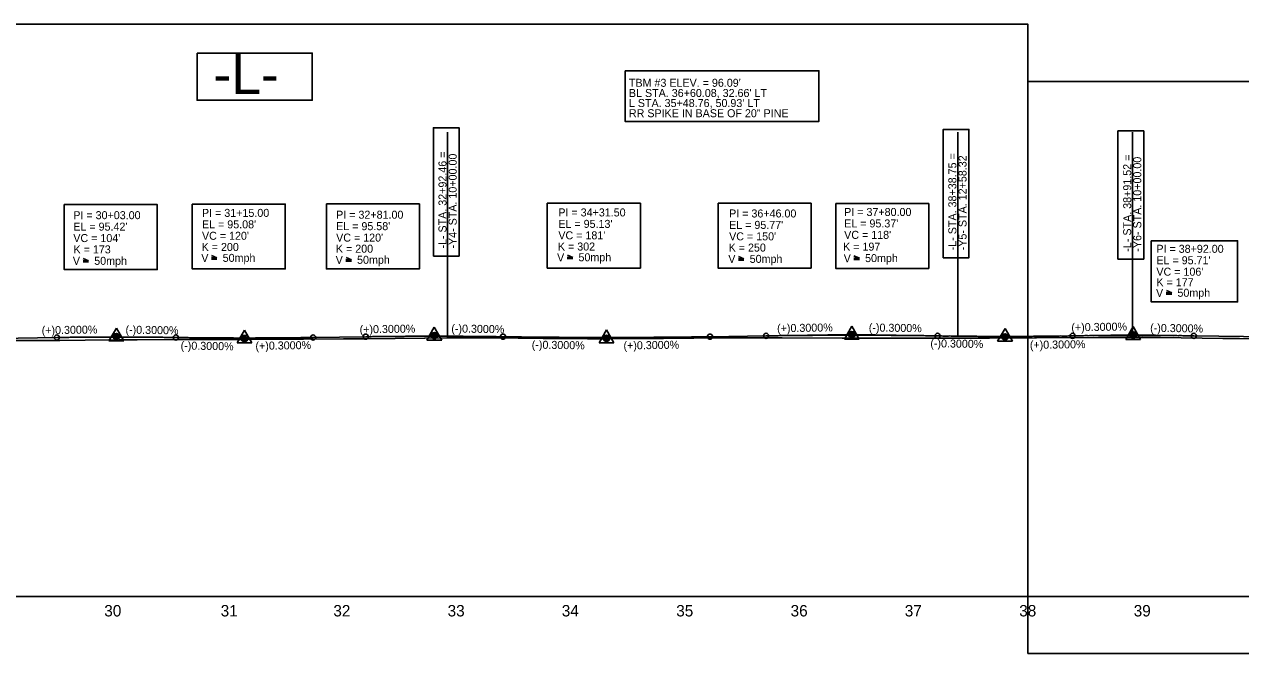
# Model space of a CAD drawing. Extents: x 2366464 to 2375718, y 801842 to 804354.
# Drawn here: x 2369240 to 2370304, y 803804 to 804354 of the extents above; entities that cross this region are included whole.
import ezdxf

# ---------------------------------------------------------------- set-up
doc = ezdxf.new("R2010")
doc.units = 0
for name, color, linetype in [('Exist Profile Cell', 7, 'Continuous'), ('Exist Vertical Profile Ground Line', 7, 'Continuous'), ('Exist Vertical Profile Horizontal Axis Label Major', 7, 'Continuous'), ('Prop Grid Mask', 7, 'Continuous'), ('Prop PFL VPI Symbol CELL', 7, 'Continuous'), ('Prop Vertical Profile Curve Label', 7, 'Continuous'), ('Prop Vertical Profile Grade', 7, 'Continuous'), ('Prop Vertical Profile Grade Label', 7, 'Continuous'), ('Prop VPI Label', 7, 'Continuous'), ('Scratch_Level_5', 7, 'Continuous'), ('Sheet Layout Profile Border Port 1', 7, 'Continuous'), ('Sheet Layout Profile Border Port 2', 7, 'Continuous')]:
    doc.layers.add(name, color=color, linetype=linetype)

# ---------------------------------------------------------------- blocks, each defined once
blk = doc.blocks.new('Profile VPI Symbol')
at = {"layer": 'Prop PFL VPI Symbol CELL'}
for p, q in [((-0.001, 0.147), (-0.13, -0.077)), ((-0.001, 0.147), (0.129, -0.077)), ((-0.13, -0.077), (0.129, -0.077))]:
    blk.add_line(p, q, dxfattribs=at)
for radius in [0.035, 0.024]:
    blk.add_circle((-0.001, -0.003), radius, dxfattribs=at)

msp = doc.modelspace()

# ---------------------------------------------------------------- linework, layer by layer
at = {"layer": 'Exist Profile Cell'}
msp.add_line((2367318, 803854), (2374481.8, 803854), dxfattribs=at)
at = {"layer": 'Exist Vertical Profile Ground Line'}
msp.add_lwpolyline([(2369218.7, 804077.6), (2369243.4, 804077.7), (2369248.7, 804077.7), (2369271.5, 804077.7), (2369293.8, 804077.9), (2369323.5, 804078.2), (2369324.7, 804078.2), (2369339, 804078.3), (2369375, 804078.5), (2369376.2, 804078.5), (2369384.1, 804078.5), (2369429.3, 804078.6), (2369430.2, 804078.6), (2369431.1, 804078.6), (2369474.4, 804078.7), (2369483.3, 804078.7), (2369484.7, 804078.7), (2369519.6, 804079), (2369536.9, 804079.2), (2369537.6, 804079.2), (2369538.1, 804079.2), (2369564.7, 804079.5), (2369590.5, 804079.8), (2369590.8, 804079.8), (2369609.8, 804079.9), (2369614.6, 804079.9), (2369619.3, 804079.9), (2369624.1, 804079.9), (2369628.8, 804079.9), (2369633.6, 804079.9), (2369642.1, 804079.9), (2369650.1, 804079.9), (2369694.1, 804079.5), (2369695.8, 804079.4), (2369724.9, 804079.3), (2369728.9, 804079.3), (2369732.8, 804079.2), (2369736.8, 804079.2), (2369740.7, 804079.2), (2369744.6, 804079.2), (2369746.4, 804079.2), (2369797.7, 804079.3), (2369799.2, 804079.3), (2369852.7, 804079.9), (2369853.2, 804079.9), (2369902.6, 804080), (2369903.2, 804080), (2369955.6, 804079.7), (2369956.7, 804079.7), (2370010, 804079.7), (2370010.8, 804079.7), (2370011.7, 804079.7), (2370069.1, 804079.7), (2370084.3, 804079.8), (2370123.6, 804079.9), (2370124.2, 804079.9), (2370125.6, 804079.9), (2370179.7, 804080.3), (2370232.6, 804080.3), (2370233.3, 804080.3), (2370233.9, 804080.3), (2370288.5, 804079.5), (2370302.9, 804079.4), (2370343.4, 804079.1)], dxfattribs=at)
at = {"layer": 'Prop Grid Mask'}
for points in [[(2369391.5, 804328.9), (2369492.2, 804328.9), (2369492.2, 804287.6), (2369391.5, 804287.6)], [(2369765.8, 804313.4), (2369935.3, 804313.4), (2369935.3, 804269.2), (2369765.8, 804269.2)], [(2369598.1, 804151.5), (2369598.1, 804263.6), (2369620.6, 804263.6), (2369620.6, 804151.5)], [(2370043.9, 804150), (2370043.9, 804262.1), (2370066.4, 804262.1), (2370066.4, 804150)], [(2370196.7, 804148.8), (2370196.7, 804260.9), (2370219.3, 804260.9), (2370219.3, 804148.8)], [(2369275.4, 804196.4), (2369356.7, 804196.4), (2369356.7, 804139.7), (2369275.4, 804139.7)], [(2369387.3, 804196.9), (2369468.6, 804196.9), (2369468.6, 804140.2), (2369387.3, 804140.2)], [(2369504.6, 804197), (2369585.9, 804197), (2369585.9, 804140.3), (2369504.6, 804140.3)], [(2369697.7, 804197.6), (2369779.1, 804197.6), (2369779.1, 804140.9), (2369697.7, 804140.9)], [(2369847, 804197.6), (2369928.4, 804197.6), (2369928.4, 804140.9), (2369847, 804140.9)], [(2369949.9, 804197.3), (2370031.2, 804197.3), (2370031.2, 804140.6), (2369949.9, 804140.6)], [(2370225.8, 804164.8), (2370301.3, 804164.8), (2370301.3, 804111.4), (2370225.8, 804111.4)]]:
    msp.add_lwpolyline(points, close=True, dxfattribs=at)
at = {"layer": 'Prop Vertical Profile Curve Label'}
for p, q in [((2369291.8, 804147.3), (2369296.6, 804147.3)), ((2369291.8, 804146.3), (2369296.6, 804146.3)), ((2369296.6, 804147.3), (2369291.9, 804149.3)), ((2369408.9, 804149.9), (2369404.2, 804151.9)), ((2369404.2, 804149.9), (2369408.9, 804149.9)), ((2369404.2, 804148.8), (2369408.9, 804148.8)), ((2369521.7, 804148.1), (2369526.4, 804148.1)), ((2369521.7, 804147.1), (2369526.4, 804147.1)), ((2369526.4, 804148.1), (2369521.8, 804150.1)), ((2369715.2, 804150.3), (2369720, 804150.3)), ((2369715.2, 804149.3), (2369720, 804149.3)), ((2369720, 804150.3), (2369715.3, 804152.3)), ((2369864.9, 804149), (2369869.6, 804149)), ((2369864.9, 804148), (2369869.6, 804148)), ((2369869.6, 804149), (2369865, 804151)), ((2369965.8, 804149.7), (2369970.6, 804149.7)), ((2369965.8, 804148.6), (2369970.6, 804148.6)), ((2369970.6, 804149.7), (2369965.9, 804151.7)), ((2370243.7, 804119.3), (2370239, 804121.3)), ((2370238.9, 804119.3), (2370243.7, 804119.3)), ((2370238.9, 804118.3), (2370243.7, 804118.3))]:
    msp.add_line(p, q, dxfattribs=at)
for centre in [(2369269, 804080.3), (2369373, 804080.3), (2369373, 804080.3), (2369493, 804080.3), (2369539, 804081), (2369659, 804081), (2369659, 804081), (2369840, 804081), (2369889, 804081.7), (2370039, 804081.7), (2370039, 804081.7), (2370157, 804081.7), (2370157, 804081.7), (2370263, 804081.7)]:
    msp.add_circle(centre, 2.25, dxfattribs=at)
at = {"layer": 'Prop Vertical Profile Grade'}
for p, q in [((2369218, 804079.5), (2369269, 804080.3)), ((2369493, 804080.3), (2369539, 804081)), ((2369840, 804081), (2369889, 804081.7)), ((2370263, 804081.7), (2370364.5, 804080.2))]:
    msp.add_line(p, q, dxfattribs=at)
for points in [[(2369269, 804080.3), (2369271.1, 804080.3), (2369273.1, 804080.4), (2369275.2, 804080.4), (2369277.3, 804080.4), (2369279.4, 804080.4), (2369281.5, 804080.5), (2369283.5, 804080.5), (2369285.6, 804080.5), (2369287.7, 804080.5), (2369289.8, 804080.5), (2369291.9, 804080.6), (2369293.9, 804080.6), (2369296, 804080.6), (2369298.1, 804080.6), (2369300.2, 804080.6), (2369302.3, 804080.6), (2369304.3, 804080.6), (2369306.4, 804080.6), (2369308.5, 804080.7), (2369310.6, 804080.7), (2369312.7, 804080.7), (2369314.7, 804080.7), (2369316.8, 804080.7), (2369318.9, 804080.7), (2369321, 804080.7), (2369323.1, 804080.7), (2369325.1, 804080.7), (2369327.2, 804080.7), (2369329.3, 804080.7), (2369331.4, 804080.7), (2369333.5, 804080.7), (2369335.5, 804080.6), (2369337.6, 804080.6), (2369339.7, 804080.6), (2369341.8, 804080.6), (2369343.9, 804080.6), (2369345.9, 804080.6), (2369348, 804080.6), (2369350.1, 804080.6), (2369352.2, 804080.5), (2369354.3, 804080.5), (2369356.3, 804080.5), (2369358.4, 804080.5), (2369360.5, 804080.5), (2369362.6, 804080.4), (2369364.7, 804080.4), (2369366.7, 804080.4), (2369368.8, 804080.4), (2369370.9, 804080.3), (2369373, 804080.3)], [(2369373, 804080.3), (2369375.4, 804080.3), (2369377.8, 804080.2), (2369380.2, 804080.2), (2369382.6, 804080.2), (2369385, 804080.1), (2369387.4, 804080.1), (2369389.8, 804080.1), (2369392.2, 804080), (2369394.6, 804080), (2369397, 804080), (2369399.4, 804080), (2369401.8, 804080), (2369404.2, 804079.9), (2369406.6, 804079.9), (2369409, 804079.9), (2369411.4, 804079.9), (2369413.8, 804079.9), (2369416.2, 804079.9), (2369418.6, 804079.9), (2369421, 804079.9), (2369423.4, 804079.9), (2369425.8, 804079.8), (2369428.2, 804079.8), (2369430.6, 804079.8), (2369433, 804079.8), (2369435.4, 804079.8), (2369437.8, 804079.8), (2369440.2, 804079.8), (2369442.6, 804079.9), (2369445, 804079.9), (2369447.4, 804079.9), (2369449.8, 804079.9), (2369452.2, 804079.9), (2369454.6, 804079.9), (2369457, 804079.9), (2369459.4, 804079.9), (2369461.8, 804079.9), (2369464.2, 804080), (2369466.6, 804080), (2369469, 804080), (2369471.4, 804080), (2369473.8, 804080), (2369476.2, 804080.1), (2369478.6, 804080.1), (2369481, 804080.1), (2369483.4, 804080.2), (2369485.8, 804080.2), (2369488.2, 804080.2), (2369490.6, 804080.3), (2369493, 804080.3)], [(2369539, 804081), (2369541.4, 804081), (2369543.8, 804081), (2369546.2, 804081.1), (2369548.6, 804081.1), (2369551, 804081.1), (2369553.4, 804081.2), (2369555.8, 804081.2), (2369558.2, 804081.2), (2369560.6, 804081.2), (2369563, 804081.3), (2369565.4, 804081.3), (2369567.8, 804081.3), (2369570.2, 804081.3), (2369572.6, 804081.3), (2369575, 804081.4), (2369577.4, 804081.4), (2369579.8, 804081.4), (2369582.2, 804081.4), (2369584.6, 804081.4), (2369587, 804081.4), (2369589.4, 804081.4), (2369591.8, 804081.4), (2369594.2, 804081.4), (2369596.6, 804081.4), (2369599, 804081.4), (2369601.4, 804081.4), (2369603.8, 804081.4), (2369606.2, 804081.4), (2369608.6, 804081.4), (2369611, 804081.4), (2369613.4, 804081.4), (2369615.8, 804081.4), (2369618.2, 804081.4), (2369620.6, 804081.4), (2369623, 804081.4), (2369625.4, 804081.3), (2369627.8, 804081.3), (2369630.2, 804081.3), (2369632.6, 804081.3), (2369635, 804081.3), (2369637.4, 804081.2), (2369639.8, 804081.2), (2369642.2, 804081.2), (2369644.6, 804081.2), (2369647, 804081.1), (2369649.4, 804081.1), (2369651.8, 804081.1), (2369654.2, 804081), (2369656.6, 804081), (2369659, 804081)], [(2369659, 804081), (2369662.6, 804080.9), (2369666.2, 804080.9), (2369669.8, 804080.8), (2369673.5, 804080.8), (2369677.1, 804080.7), (2369680.7, 804080.7), (2369684.3, 804080.7), (2369687.9, 804080.6), (2369691.6, 804080.6), (2369695.2, 804080.5), (2369698.8, 804080.5), (2369702.4, 804080.5), (2369706, 804080.5), (2369709.7, 804080.4), (2369713.3, 804080.4), (2369716.9, 804080.4), (2369720.5, 804080.4), (2369724.1, 804080.4), (2369727.8, 804080.3), (2369731.4, 804080.3), (2369735, 804080.3), (2369738.6, 804080.3), (2369742.2, 804080.3), (2369745.9, 804080.3), (2369749.5, 804080.3), (2369753.1, 804080.3), (2369756.7, 804080.3), (2369760.3, 804080.3), (2369764, 804080.3), (2369767.6, 804080.3), (2369771.2, 804080.3), (2369774.8, 804080.4), (2369778.4, 804080.4), (2369782.1, 804080.4), (2369785.7, 804080.4), (2369789.3, 804080.4), (2369792.9, 804080.5), (2369796.5, 804080.5), (2369800.2, 804080.5), (2369803.8, 804080.5), (2369807.4, 804080.6), (2369811, 804080.6), (2369814.6, 804080.7), (2369818.3, 804080.7), (2369821.9, 804080.7), (2369825.5, 804080.8), (2369829.1, 804080.8), (2369832.7, 804080.9), (2369836.4, 804080.9), (2369840, 804081)], [(2369889, 804081.7), (2369892, 804081.8), (2369895, 804081.8), (2369898, 804081.8), (2369901, 804081.9), (2369904, 804081.9), (2369907, 804082), (2369910, 804082), (2369913, 804082), (2369916, 804082), (2369919, 804082.1), (2369922, 804082.1), (2369925, 804082.1), (2369928, 804082.1), (2369931, 804082.2), (2369934, 804082.2), (2369937, 804082.2), (2369940, 804082.2), (2369943, 804082.2), (2369946, 804082.2), (2369949, 804082.3), (2369952, 804082.3), (2369955, 804082.3), (2369958, 804082.3), (2369961, 804082.3), (2369964, 804082.3), (2369967, 804082.3), (2369970, 804082.3), (2369973, 804082.3), (2369976, 804082.3), (2369979, 804082.3), (2369982, 804082.2), (2369985, 804082.2), (2369988, 804082.2), (2369991, 804082.2), (2369994, 804082.2), (2369997, 804082.2), (2370000, 804082.1), (2370003, 804082.1), (2370006, 804082.1), (2370009, 804082.1), (2370012, 804082), (2370015, 804082), (2370018, 804082), (2370021, 804082), (2370024, 804081.9), (2370027, 804081.9), (2370030, 804081.8), (2370033, 804081.8), (2370036, 804081.8), (2370039, 804081.7)], [(2370039, 804081.7), (2370041.3, 804081.7), (2370043.7, 804081.6), (2370046.1, 804081.6), (2370048.4, 804081.6), (2370050.8, 804081.6), (2370053.1, 804081.5), (2370055.5, 804081.5), (2370057.9, 804081.5), (2370060.2, 804081.5), (2370062.6, 804081.4), (2370064.9, 804081.4), (2370067.3, 804081.4), (2370069.7, 804081.4), (2370072, 804081.4), (2370074.4, 804081.3), (2370076.7, 804081.3), (2370079.1, 804081.3), (2370081.5, 804081.3), (2370083.8, 804081.3), (2370086.2, 804081.3), (2370088.5, 804081.3), (2370090.9, 804081.3), (2370093.3, 804081.3), (2370095.6, 804081.3), (2370098, 804081.3), (2370100.3, 804081.3), (2370102.7, 804081.3), (2370105.1, 804081.3), (2370107.4, 804081.3), (2370109.8, 804081.3), (2370112.1, 804081.3), (2370114.5, 804081.3), (2370116.9, 804081.3), (2370119.2, 804081.3), (2370121.6, 804081.3), (2370123.9, 804081.4), (2370126.3, 804081.4), (2370128.7, 804081.4), (2370131, 804081.4), (2370133.4, 804081.4), (2370135.7, 804081.5), (2370138.1, 804081.5), (2370140.5, 804081.5), (2370142.8, 804081.5), (2370145.2, 804081.6), (2370147.5, 804081.6), (2370149.9, 804081.6), (2370152.3, 804081.6), (2370154.6, 804081.7), (2370157, 804081.7)], [(2370157, 804081.7), (2370159.1, 804081.7), (2370161.2, 804081.8), (2370163.3, 804081.8), (2370165.5, 804081.8), (2370167.6, 804081.9), (2370169.7, 804081.9), (2370171.8, 804081.9), (2370173.9, 804081.9), (2370176.1, 804081.9), (2370178.2, 804082), (2370180.3, 804082), (2370182.4, 804082), (2370184.5, 804082), (2370186.7, 804082), (2370188.8, 804082), (2370190.9, 804082.1), (2370193, 804082.1), (2370195.1, 804082.1), (2370197.3, 804082.1), (2370199.4, 804082.1), (2370201.5, 804082.1), (2370203.6, 804082.1), (2370205.7, 804082.1), (2370207.9, 804082.1), (2370210, 804082.1), (2370212.1, 804082.1), (2370214.2, 804082.1), (2370216.3, 804082.1), (2370218.5, 804082.1), (2370220.6, 804082.1), (2370222.7, 804082.1), (2370224.8, 804082.1), (2370226.9, 804082.1), (2370229.1, 804082.1), (2370231.2, 804082), (2370233.3, 804082), (2370235.4, 804082), (2370237.5, 804082), (2370239.7, 804082), (2370241.8, 804082), (2370243.9, 804081.9), (2370246, 804081.9), (2370248.1, 804081.9), (2370250.3, 804081.9), (2370252.4, 804081.9), (2370254.5, 804081.8), (2370256.6, 804081.8), (2370258.7, 804081.8), (2370260.9, 804081.7), (2370263, 804081.7)]]:
    msp.add_spline(points, degree=3, dxfattribs=at)
at = {"layer": 'Prop VPI Label'}
for p, q in [((2369610.4, 804081.4), (2369610.4, 804259.8)), ((2370056.7, 804081.5), (2370056.7, 804259.8)), ((2370209.5, 804082.1), (2370209.5, 804259.8)), ((2369269, 804080.3), (2369318.2, 804081)), ((2369373, 804080.3), (2369323.7, 804081)), ((2369373, 804080.3), (2369430.2, 804079.4)), ((2369493, 804080.3), (2369435.7, 804079.4)), ((2369539, 804081), (2369596.2, 804081.8)), ((2369659, 804081), (2369601.7, 804081.8)), ((2369659, 804081), (2369746.7, 804079.7)), ((2369840, 804081), (2369752.2, 804079.7)), ((2369889, 804081.7), (2369961.2, 804082.8)), ((2370039, 804081.7), (2369966.7, 804082.8)), ((2370039, 804081.7), (2370095.2, 804080.9)), ((2370157, 804081.7), (2370100.7, 804080.9)), ((2370157, 804081.7), (2370207.2, 804082.5)), ((2370263, 804081.7), (2370212.7, 804082.5))]:
    msp.add_line(p, q, dxfattribs=at)
for centre in [(2369321, 804081.1), (2369433, 804079.4), (2369599, 804081.9), (2369749.5, 804079.6), (2369964, 804082.8), (2370098, 804080.8), (2370210, 804082.5)]:
    msp.add_circle(centre, 2.75, dxfattribs=at)
at = {"layer": 'Scratch_Level_5'}
for p, q in [((2369401, 804079.8), (2369401, 804079.8)), ((2369618, 804080.5), (2369618, 804080.5)), ((2369744, 804080.3), (2369744, 804080.3)), ((2369899, 804081.4), (2369899, 804081.4)), ((2369899, 804081.4), (2369899, 804081.4)), ((2370068, 804081.2), (2370068, 804081.2)), ((2370218, 804081.1), (2370218, 804081.1))]:
    msp.add_line(p, q, dxfattribs=at)
at = {"layer": 'Sheet Layout Profile Border Port 1'}
msp.add_lwpolyline([(2370118, 803804), (2371518, 803804), (2371518, 804304), (2370118, 804304)], close=True, dxfattribs=at)
at = {"layer": 'Sheet Layout Profile Border Port 2'}
msp.add_lwpolyline([(2368718, 803854), (2370118, 803854), (2370118, 804354), (2368718, 804354)], close=True, dxfattribs=at)

# ---------------------------------------------------------------- block references
at = {"layer": 'Prop Grid Mask', "xscale": 50, "yscale": 50}
for p in [(2369599, 804081.9), (2369964, 804082.8), (2370210, 804082.5), (2369321, 804081.1), (2369433, 804079.4), (2369749.5, 804079.6), (2370098, 804080.8)]:
    msp.add_blockref('Profile VPI Symbol', p, dxfattribs=at)

# ---------------------------------------------------------------- texts
at = {"layer": 'Exist Vertical Profile Horizontal Axis Label Major'}
for s, p in [('30', (2369310.4, 803836.5)), ('31', (2369412.2, 803836.5)), ('32', (2369510.7, 803836.5)), ('33', (2369610.6, 803836.5)), ('34', (2369710.4, 803836.5)), ('35', (2369810.5, 803836.5)), ('36', (2369910.5, 803836.5)), ('37', (2370010.3, 803836.5)), ('38', (2370110.4, 803836.5)), ('39', (2370210.5, 803836.5))]:
    msp.add_text(s, height=10, dxfattribs=at).set_placement(p)
at = {"layer": 'Prop Vertical Profile Curve Label'}
for s, p in [('-L- STA. 32+92.46 = ', (2369609.6, 804158)), ('-Y4- STA. 10+00.00', (2369618.5, 804158)), ('-L- STA. 38+38.75 = ', (2370055.4, 804156.5)), ('-Y5- STA. 12+58.32', (2370064.3, 804156.5)), ('-L- STA. 38+91.52 = ', (2370208.3, 804155.3)), ('-Y6- STA. 10+00.00', (2370217.1, 804155.3))]:
    msp.add_text(s, height=7, rotation=90, dxfattribs=at).set_placement(p)
for s, p in [("VC = 104'", (2369283.3, 804163.7)), ("VC = 120'", (2369395.8, 804165.7)), ("VC = 120'", (2369513.1, 804164.1)), ("VC = 181'", (2369707.4, 804166.1)), ("VC = 150'", (2369856.7, 804165.2)), ("VC = 118'", (2369957.3, 804166.5)), ('K = 173', (2369283.5, 804153.8)), ('V', (2369395.2, 804146.3)), ('K = 200', (2369395.5, 804155.9)), ('50mph', (2369413.9, 804146.4)), ('K = 200', (2369512.9, 804154.4)), ('V', (2369706.3, 804146.8)), ('K = 302', (2369707, 804156.3)), ('50mph', (2369725, 804146.9)), ('K = 250', (2369856.3, 804155.4)), ('50mph', (2369874.7, 804145.5)), ('V', (2369956.9, 804146.1)), ('K = 197', (2369956.4, 804156.2)), ('50mph', (2369975.6, 804146.2)), ('V', (2369282.9, 804143.8)), ('50mph', (2369301.6, 804143.8)), ('V', (2369512.7, 804144.6)), ('50mph', (2369531.4, 804144.7)), ('V', (2369856, 804145.5)), ("VC = 106'", (2370230.3, 804134.3)), ('K = 177', (2370230.3, 804125.1)), ('V', (2370230, 804115.8)), ('50mph', (2370248.7, 804115.9))]:
    msp.add_text(s, height=7, dxfattribs=at).set_placement(p)
at = {"layer": 'Prop Vertical Profile Grade Label'}
for s, rotation, p in [('(+)0.3000%', 0.8594, (2369255.7, 804083.1)), ('(-)0.3000%', 359.1406, (2369328.9, 804083.7)), ('(+)0.3000%', 0.8594, (2369533.7, 804083.9)), ('(-)0.3000%', 359.1406, (2369613.8, 804084.7)), ('(+)0.3000%', 0.8594, (2369898.7, 804084.9)), ('(-)0.3000%', 359.1406, (2369978.8, 804085.6)), ('(+)0.3000%', 0.8594, (2370156, 804085.7)), ('(-)0.3000%', 359.1406, (2370224.8, 804085.3)), ('(-)0.3000%', 359.1406, (2370032.6, 804071.8)), ('(-)0.3000%', 359.1406, (2369377.1, 804069.8)), ('(+)0.3000%', 0.8594, (2369442.6, 804069.5)), ('(-)0.3000%', 359.1406, (2369684.1, 804070.6)), ('(+)0.3000%', 0.8594, (2369764.4, 804069.8)), ('(+)0.3000%', 0.8594, (2370119.7, 804070.3))]:
    msp.add_text(s, height=7, rotation=rotation, dxfattribs=at).set_placement(p)
at = {"layer": 'Prop VPI Label'}
for s, height, p in [('-L-', 35, (2369405.8, 804293.1)), ("TBM #3 ELEV. = 96.09'", 7, (2369769.1, 804299.4)), ("BL STA. 36+60.08, 32.66' LT", 7, (2369769.1, 804290.5)), ("L STA. 35+48.76, 50.93' LT", 7, (2369769.1, 804281.7)), ('RR SPIKE IN BASE OF 20" PINE', 7, (2369769.1, 804272.8)), ('PI = 30+03.00', 7, (2369283.3, 804183.7)), ('PI = 31+15.00', 7, (2369395.8, 804185.7)), ('PI = 32+81.00', 7, (2369513.1, 804184.1)), ('PI = 34+31.50', 7, (2369707.4, 804186.1)), ('PI = 36+46.00', 7, (2369856.7, 804185.2)), ('PI = 37+80.00', 7, (2369957.3, 804186.5)), ("EL = 95.42'", 7, (2369283.3, 804173.7)), ("EL = 95.08'", 7, (2369395.8, 804175.7)), ("EL = 95.58'", 7, (2369513.1, 804174.1)), ("EL = 95.13'", 7, (2369707.4, 804176.1)), ("EL = 95.77'", 7, (2369856.7, 804175.2)), ("EL = 95.37'", 7, (2369957.3, 804176.5)), ('PI = 38+92.00', 7, (2370230.3, 804154.3)), ("EL = 95.71'", 7, (2370230.3, 804144.3))]:
    msp.add_text(s, height=height, dxfattribs=at).set_placement(p)

doc.saveas('drawing.dxf')
